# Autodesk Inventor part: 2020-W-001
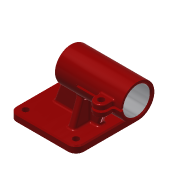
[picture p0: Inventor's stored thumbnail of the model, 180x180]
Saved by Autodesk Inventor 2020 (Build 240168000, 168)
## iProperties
Created: 2013-12
Part Number: 2020-W-001
Material: Aluminium 6061
Document SubType Name: Modeling
Designer: F.Stasiak
Density: 2.7 g/cm^3
Appearance: Czerwona
Description: Mocowanie rurki D=48 mm
Mass: 1046.34 g
Surface Area: 867.627 cm^2
Volume: 387.533 cm^3
Manager: www.cadconsulting.pl
Company: Fabian Stasiak CAD Consulting
Author: F.Stasiak
Subject: Zbiór ćwiczeń. Autodesk Inventor 2020. Kurs podstawowy
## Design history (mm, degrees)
sketch "Szkic1"
  geometry: L1 (60, -60)-(-60, -60); L2 (-60, -60)-(-60, 60); L3 (-60, 60)-(60, 60); L4 (60, 60)-(60, -60); L5 (60, -60)-(-60, 60); L6 (-60, -60)-(60, 60); 1 further point
  constraints: 12 end point, 2 midpoint, 2 parallel, 1 horizontal, 1 perpendicular
  dimensions: "d0" = 120 distance of L2.end L3.end; "d1" = 120 distance of L1.end L2.end
extrude "Wyciągnięcie proste1" new body sketch "Szkic1" distance "d2" = 12; taper "d3" = 0 deg
sketch "Szkic2"
  geometry: L1 (-10, 80)-(110, 80); L2 (110, 80)-(110, 110); L3 (110, 110)-(-10, 110); L4 (-10, 110)-(-10, 80); L5 (60, 0)-(60, 12) reference; L6 (60, 0)-(-60, 0) reference; 1 further point
  constraints: 8 end point, 2 parallel, 1 horizontal, 1 perpendicular
  dimensions: "d4" = 120 distance of L3.end L2.end; "d6" = 60 diameter of L3 L1; "d7" = 50 distance between parallel lines of L5 L2; "d8" = 80 distance between parallel lines of L1 L6
revolve "Obrót1" sketch "Szkic2" stored, may be unused: angle "d9" = 90 deg
sketch "Szkic3"
  geometry: L1 (-60, 0)-(-60, 12) reference; L2 (-60, 12)-(60, 12) reference; L3 (60, 12)-(60, 0) reference; L4 (60, 0)-(-60, 0) reference; L5 (-10, 50)-(-10, 110) reference; L6 (-10, 110)-(110, 110) reference; L7 (110, 110)-(110, 50) reference; L8 (110, 50)-(-10, 50) reference; L9 (-34.75, 12)-(-10, 80); L10 (45.25, 12)-(70, 80); L11 (-10, 80)-(70, 80); 1 further point
  constraints: 6 end point, 2 parallel, 2 point on line, 1 midpoint
  dimensions: "d10" = 70 deg angle of L9 L2; "d11" = 80 distance of L9.end L10.end
extrude "Wyciągnięcie proste2" join sketch "Szkic3" stored distance "d12" = 12; taper "d13" = 0 deg
node "Płaszczyzna konstrukcyjna1"
sketch "Szkic4"
  geometry: L1 (120, 12)-(120, 0) reference; L2 (120, 0)-(0, 0) reference; L3 (0, 0)-(0, 12) reference; L4 (0, 12)-(54, 12) reference; L5 (54, 12)-(54, 50.606) reference; L6 (66, 50.606)-(66, 12) reference; L7 (66, 12)-(120, 12) reference; L8 (25, 12)-(41.232, 56.596); A1 r 30 centre (60, 80) between (66, 50.606) and (54, 50.606) reference; 1 further point
  constraints: 2 end point, 1 point on circle, 1 point on line
  dimensions: "d14" = 70 deg angle of L8 L4; "d16" = 25 distance from line of L8.start L3
extrude "Wyciągnięcie proste3" join sketch "Szkic4" stored distance "d17" = 12; taper "d18" = 0 deg
mirror "Odbicie lustrzane1"
node "Płaszczyzna konstrukcyjna2"
  node "Oś konstrukcyjna1"
sketch "Szkic5"
  geometry: L1 (-60, -6)-(-60, 6) reference; L2 (-60, 6)-(-60, 30) reference; L3 (-60, 30)-(60, 30) reference; L4 (60, 30)-(60, -30) reference; L5 (60, -30)-(-60, -30) reference; L6 (-60, -30)-(-60, -6) reference; L7 (47, 0)-(47, -40); L8 (23, -40)-(23, 0); L9 (23, 0)-(47, 0); L10 (-144, 0)-(94, 0) reference; A1 r 12 centre (35, -40) between (23, -40) and (47, -40); 1 further point
  constraints: 6 end point, 2 parallel, 2 point on circle, 2 tangent, 1 centre point, 1 collinear, 1 perpendicular
  dimensions: "d20" = 12 radius of A1; "d21" = 25 distance from line of L4 A1.centre; "d22" = 40 distance from line of L9 A1.centre
extrude "Wyciągnięcie proste4" join sketch "Szkic5" stored distance "d23" = 20; taper "d24" = 0 deg
sketch "Szkic6"
  geometry: C1 r 30 at (0, 0) reference; C2 r 24 at (0, 0); 1 further point
  constraints: 1 centre point, 1 coincident
  dimensions: "d25" = 48 diameter of C2
extrude "Wyciągnięcie proste5" cut sketch "Szkic6" distance "d26" = 100; taper "d27" = 0 deg
sketch "Szkic8"
  geometry: L1 (-52, -10)-(-52, 10) reference; L2 (-52, 2)-(0, 2); L3 (0, 2)-(0, -2); L4 (0, -2)-(-52, -2); L5 (-52, -2)-(-52, 2); C1 r 24 at (0, 0) reference; 2 further points
  constraints: 8 end point, 2 parallel, 1 coincident, 1 collinear, 1 horizontal, 1 midpoint, 1 perpendicular
  dimensions: "d28" = 4 distance between parallel lines of L2 L4
extrude "Wyciągnięcie proste6" cut sketch "Szkic8" distance "d29" = 80; taper "d30" = 0 deg
hole "Otwór1" diameter "d33" = 11; stored, may be unused: countersink angle "d37" = 90 deg, drill point angle "d39" = 118 deg; dims "d31" = 10, "d32" = 10, "d34" = 6, "d35" = 4, "d36" = 2, "d38" = 8
sketch "Szkic9"
  geometry: L1 (60, 60)-(-60, 60) reference; L2 (-60, 60)-(-60, -60) reference; L3 (-60, -60)-(60, -60) reference; L4 (60, -60)-(60, 60) reference; L5 (-45, 45)-(45, 45); L6 (45, 45)-(45, -45); L7 (45, -45)-(-45, -45); L8 (-45, -45)-(-45, 45); 1 further point
  constraints: 8 end point, 3 other
  dimensions: "d40" = 15 distance between parallel lines of L1 L5
hole "Otwór2" sketch "Szkic9" at (-45, 45), (45, 45), (45, -45), (-45, -45) diameter "d41" = 11; stored, may be unused: countersink angle "d45" = 90 deg, drill point angle "d47" = 118 deg; dims "d42" = 6, "d43" = 4, "d44" = 2, "d46" = 8
fillet "Zaokrąglenie1" dims "d48" = 2
fillet "Zaokrąglenie2" dims "d49" = 4
fillet "Zaokrąglenie3" dims "d50" = 4
fillet "Zaokrąglenie4" dims "d51" = 4
fillet "Zaokrąglenie5" dims "d52" = 14
chamfer "Faza1" distance "d53" = 2; stored, may be unused: second distance "d54" = 2, angle "d55" = 45 deg
fillet "Zaokrąglenie6" dims "d56" = 2
node "Bryła1"
node "Rzutuj krawędzie tnące1"
node "Rzutuj krawędzie tnące2"
node "Rzutuj krawędzie tnące3"
other parameters: "d19" = 0
